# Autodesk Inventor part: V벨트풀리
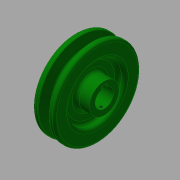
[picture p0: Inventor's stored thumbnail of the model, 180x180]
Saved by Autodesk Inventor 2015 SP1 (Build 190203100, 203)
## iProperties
Created: 2015-11
Part Number: V벨트풀리
Material: 강철, 탄소
Document SubType Name: Modeling
Designer: mduedu
Density: 1 g/cm^3
Appearance: 진녹색
Author: mduedu
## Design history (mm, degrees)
sketch "스케치1"
  geometry: L1 (-9.5, 0)-(9.5, 0); L2 (0, 0)-(0, 37.7); L3 (-4.825, 37.7)-(-9.5, 37.7); L4 (-9.5, 37.7)-(-9.5, 0); L5 (0, 28.7)-(-2.074, 28.7); L6 (-2.074, 28.7)-(-4.825, 37.7); L7 (4.825, 37.7)-(9.5, 37.7); L8 (9.5, 37.7)-(9.5, 0); L9 (0, 28.7)-(2.074, 28.7); L10 (2.074, 28.7)-(4.825, 37.7); L11 (-9.5, 35)-(9.5, 35); 3 further points
  constraints: 22 end point, 7 point on line, 4 perpendicular, 3 symmetric about line, 1 coincident, 1 horizontal, 1 horizontal alignment, 1 midpoint, 1 vertical
  dimensions: "d0" = 19 distance of L1.start L1.end; "d2" = 75.4 diameter of L2.end L1 (derived); "d3" = 34 deg angle of L10 L6; "d4" = 6.3 distance between parallel lines of L11 L9; "d5" = 2.7 distance between parallel lines of L7 L11; "d6" = 8 distance of point (4, 35) point (-4, 35); "d7" = 70 diameter of L11 L1
revolve "회전1" sketch "스케치1" stored, may be unused: angle "d8" = 90 deg
sketch "스케치2"
  geometry: C1 r 24 at (0, 0); C2 r 13 at (0, 0); 1 further point
  constraints: 2 centre point, 2 coincident
  dimensions: "d9" = 48 diameter of C1; "d10" = 26 diameter of C2
extrude "돌출1" cut sketch "스케치2" distance "d11" = 6; taper "d12" = 0 deg
extrude "돌출3" join sketch "스케치2" distance "d37" = 6; taper "d38" = 0 deg
fillet "모깎기1" dims "d13" = 3
fillet "모깎기2" dims "d14" = 3
fillet "모깎기3" dims "d15" = 1, "d16" = 0.5, "d17" = 2
hole "구멍1" diameter "d20" = 16; stored, may be unused: countersink angle "d24" = 90 deg, drill point angle "d26" = 118 deg; dims "d21" = 6, "d22" = 4, "d23" = 2, "d25" = 8, "d53" = 10, "d54" = 10
sketch "스케치3"
  geometry: L1 (-2.5, 0)-(2.5, 0); L2 (2.5, 0)-(2.5, 10.3); L3 (2.5, 10.3)-(-2.5, 10.3); L4 (-2.5, 10.3)-(-2.5, 0); 2 further points
  constraints: 8 end point, 2 parallel, 1 coincident, 1 horizontal, 1 midpoint, 1 perpendicular
  dimensions: "d27" = 5 distance of L2.end L3.end; "d29" = 10.3 distance of L3.end L1.start
extrude "돌출2" cut sketch "스케치3" stored distance "d30" = 6; taper "d31" = 0 deg
node "작업 평면1"
sketch "스케치4"
  geometry: L1 (19, -27)-(19, 27) reference; 2 further points
  constraints: 1 horizontal alignment
  dimensions: "d52" = 22 distance from line of L1 point (-3, 0)
hole "구멍2" sketch "스케치4" at (-3, 0) diameter "d42" = 2.459; stored, may be unused: countersink angle "d46" = 90 deg, drill point angle "d48" = 118 deg; dims "d43" = 6, "d44" = 4, "d45" = 2, "d47" = 8
node "솔리드1"
mirror "대칭1"
